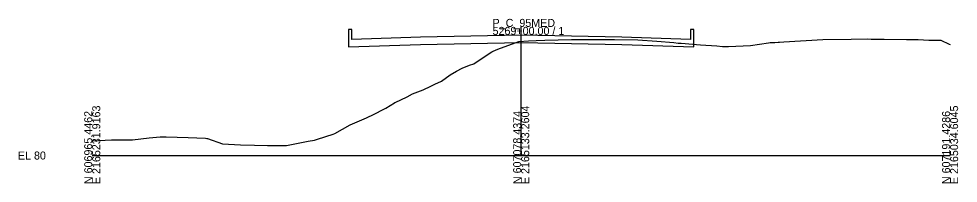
# Model space of a CAD drawing. Extents: x -26 to 303, y -10 to 10517.
# Drawn here: x -25.7 to 302.8, y 4490.3 to 4547.8 of the extents above; entities that cross this region are included whole.
import ezdxf

# ---------------------------------------------------------------- set-up
doc = ezdxf.new("R2010")
doc.units = 0
for name, color, linetype in [('RD_GPK_XS_Cell', 7, 'Continuous'), ('RD_PD_Final_TrvlWay', 7, 'Continuous'), ('RD_XS_ExGround', 7, 'Continuous')]:
    doc.layers.add(name, color=color, linetype=linetype)

msp = doc.modelspace()

# ---------------------------------------------------------------- linework, layer by layer
at = {"layer": 'RD_GPK_XS_Cell'}
for p, q in [((150, 4500), (150, 4545)), ((0, 4500), (150, 4500)), ((150, 4500), (300, 4500))]:
    msp.add_line(p, q, dxfattribs=at)
at = {"layer": 'RD_PD_Final_TrvlWay'}
for p, q in [((90.75, 4544.12), (89.62, 4544.12)), ((89.62, 4544.12), (89.62, 4544.12)), ((89.62, 4544.12), (89.62, 4538.03)), ((90.83, 4540.62), (90.75, 4544.12)), ((209.25, 4544.12), (209.17, 4540.62)), ((210.38, 4544.12), (209.25, 4544.12)), ((209.25, 4544.12), (209.25, 4544.12)), ((210.38, 4538.03), (210.38, 4544.12)), ((114.83, 4541.39), (90.83, 4540.62)), ((90.83, 4540.62), (90.83, 4540.62)), ((90.83, 4540.62), (90.83, 4540.62)), ((150, 4542.1), (114.83, 4541.39)), ((114.83, 4541.39), (114.83, 4541.39)), ((185.17, 4541.39), (150, 4542.1)), ((209.17, 4540.62), (185.17, 4541.39)), ((185.17, 4541.39), (185.17, 4541.39)), ((209.17, 4540.62), (209.17, 4540.62)), ((209.17, 4540.62), (209.17, 4540.62)), ((89.62, 4538.03), (114.83, 4538.83)), ((89.62, 4538.03), (89.62, 4538.03)), ((89.62, 4538.03), (89.62, 4538.03)), ((114.83, 4538.83), (150, 4539.54)), ((114.83, 4538.83), (114.83, 4538.83)), ((150, 4539.54), (185.17, 4538.83)), ((185.17, 4538.83), (185.17, 4538.83)), ((185.17, 4538.83), (210.38, 4538.03)), ((210.38, 4538.03), (210.38, 4538.03)), ((210.38, 4538.03), (210.38, 4538.03))]:
    msp.add_line(p, q, dxfattribs=at)
at = {"layer": 'RD_XS_ExGround'}
msp.add_lwpolyline([(0, 4505.14), (6.7, 4505.43), (9.45, 4505.47), (10.34, 4505.5), (14.11, 4505.49), (19.89, 4506.17), (23.7, 4506.5), (24.69, 4506.58), (25.9, 4506.53), (33.59, 4506.34), (39.66, 4506.02), (40.12, 4506), (40.26, 4505.94), (45.53, 4504.11), (51.9, 4503.69), (56.76, 4503.57), (61.26, 4503.5), (67.96, 4503.46), (75.55, 4505.04), (77.77, 4505.37), (78.74, 4505.72), (84.28, 4507.42), (84.88, 4507.72), (90.14, 4510.69), (95.9, 4513.23), (96.57, 4513.54), (97.86, 4514.16), (102.64, 4516.51), (105.67, 4518.42), (105.83, 4518.52), (105.99, 4518.58), (110.13, 4520.54), (112, 4521.64), (115.73, 4523.01), (118.37, 4524.27), (119.78, 4524.91), (122.14, 4526.02), (125.13, 4528.25), (127.39, 4529.55), (129.34, 4530.52), (131.89, 4531.58), (133.41, 4532.04), (139.18, 4535.87), (139.71, 4536.24), (140.19, 4536.55), (141.86, 4537.16), (149.13, 4539.89), (152.56, 4540.07), (155.29, 4540.2), (158.33, 4540.34), (167.56, 4540.54), (170.66, 4540.58), (174.19, 4540.63), (174.43, 4540.61), (174.53, 4540.65), (176.02, 4540.65), (182.66, 4540.62), (190.82, 4540.51), (197.49, 4540), (203.33, 4539.52), (204.87, 4539.35), (205.91, 4539.26), (212.73, 4538.77), (218.43, 4538.32), (220.42, 4538.16), (222.47, 4538.2), (230.22, 4538.5), (236.51, 4539.42), (237.07, 4539.5), (238.66, 4539.51), (239.84, 4539.64), (240.36, 4539.65), (241.83, 4539.73), (255.49, 4540.57), (265.44, 4540.7), (271.15, 4540.8), (272.44, 4540.75), (276.91, 4540.72), (284.73, 4540.6), (288.88, 4540.55), (292.53, 4540.41), (294.88, 4540.39), (296.75, 4540.33), (299.73, 4538.95), (300, 4538.83)], dxfattribs=at)

# ---------------------------------------------------------------- texts
at = {"layer": 'RD_GPK_XS_Cell'}
for s, p in [('P_C_95MED', (140, 4545)), ('5269+00.00 / 1', (140, 4542.2)), ('EL 80', (-26, 4498.6))]:
    msp.add_text(s, height=2.8, dxfattribs=at).set_placement(p)
for s, p in [('E 2165133.2604', (152.8, 4490)), ('E 2165034.6045', (302.8, 4490)), ('N 606965.4462', (0, 4490)), ('E 2165231.9163', (2.8, 4490)), ('N 607078.4374', (150, 4490)), ('N 607191.4286', (300, 4490))]:
    msp.add_text(s, height=2.8, rotation=90, dxfattribs=at).set_placement(p)

doc.saveas('drawing.dxf')
